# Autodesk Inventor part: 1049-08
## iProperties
Created: 2007-03
Part Number: 1049-08
Document SubType Name: Modeling
Designer: Andy Moles
Material: Acetal Resin, Black
Mass: 0.928303 g
Surface Area: 5.66995 cm^2
Volume: 0.651441 cm^3
Density: 1.425 g/cm^3
Author: Andy Moles
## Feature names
1. Extrusion1
